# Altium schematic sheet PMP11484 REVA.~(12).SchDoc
size 431 x 279 mm; Date: Not shown in title block; ApprovedBy: Not shown in title block; CheckedBy: Not shown in title block; Author: Not shown in title block; CompanyName: Not shown in title block; Engineer: Not shown in title block; Organization: Not shown in title block; Address1: Not shown in title block; Address2: Not shown in title block; Address3: Not shown in title block; Address4: Not shown in title block; DocumentNumber: 1; Revision: Use project parameter SCH_Rev; SheetNumber: 1; SheetTotal: 1; PageSetup: Record=PageOptions¦CenterHorizontal=True¦CenterVertical=True¦PrintScale=1.00¦XCorrection=1.00¦YCorrection=1.00¦PrintKind=0¦BorderSize=5000000¦LeftOffset=0¦BottomOffset=0¦Orientation=2¦PaperLength=1000¦PaperWidth=1000¦Scale=100¦PaperSource=15¦PrintQuality=600¦MediaType=1¦DitherType=10¦PaperKind=Letter¦PrintScaleMode=1
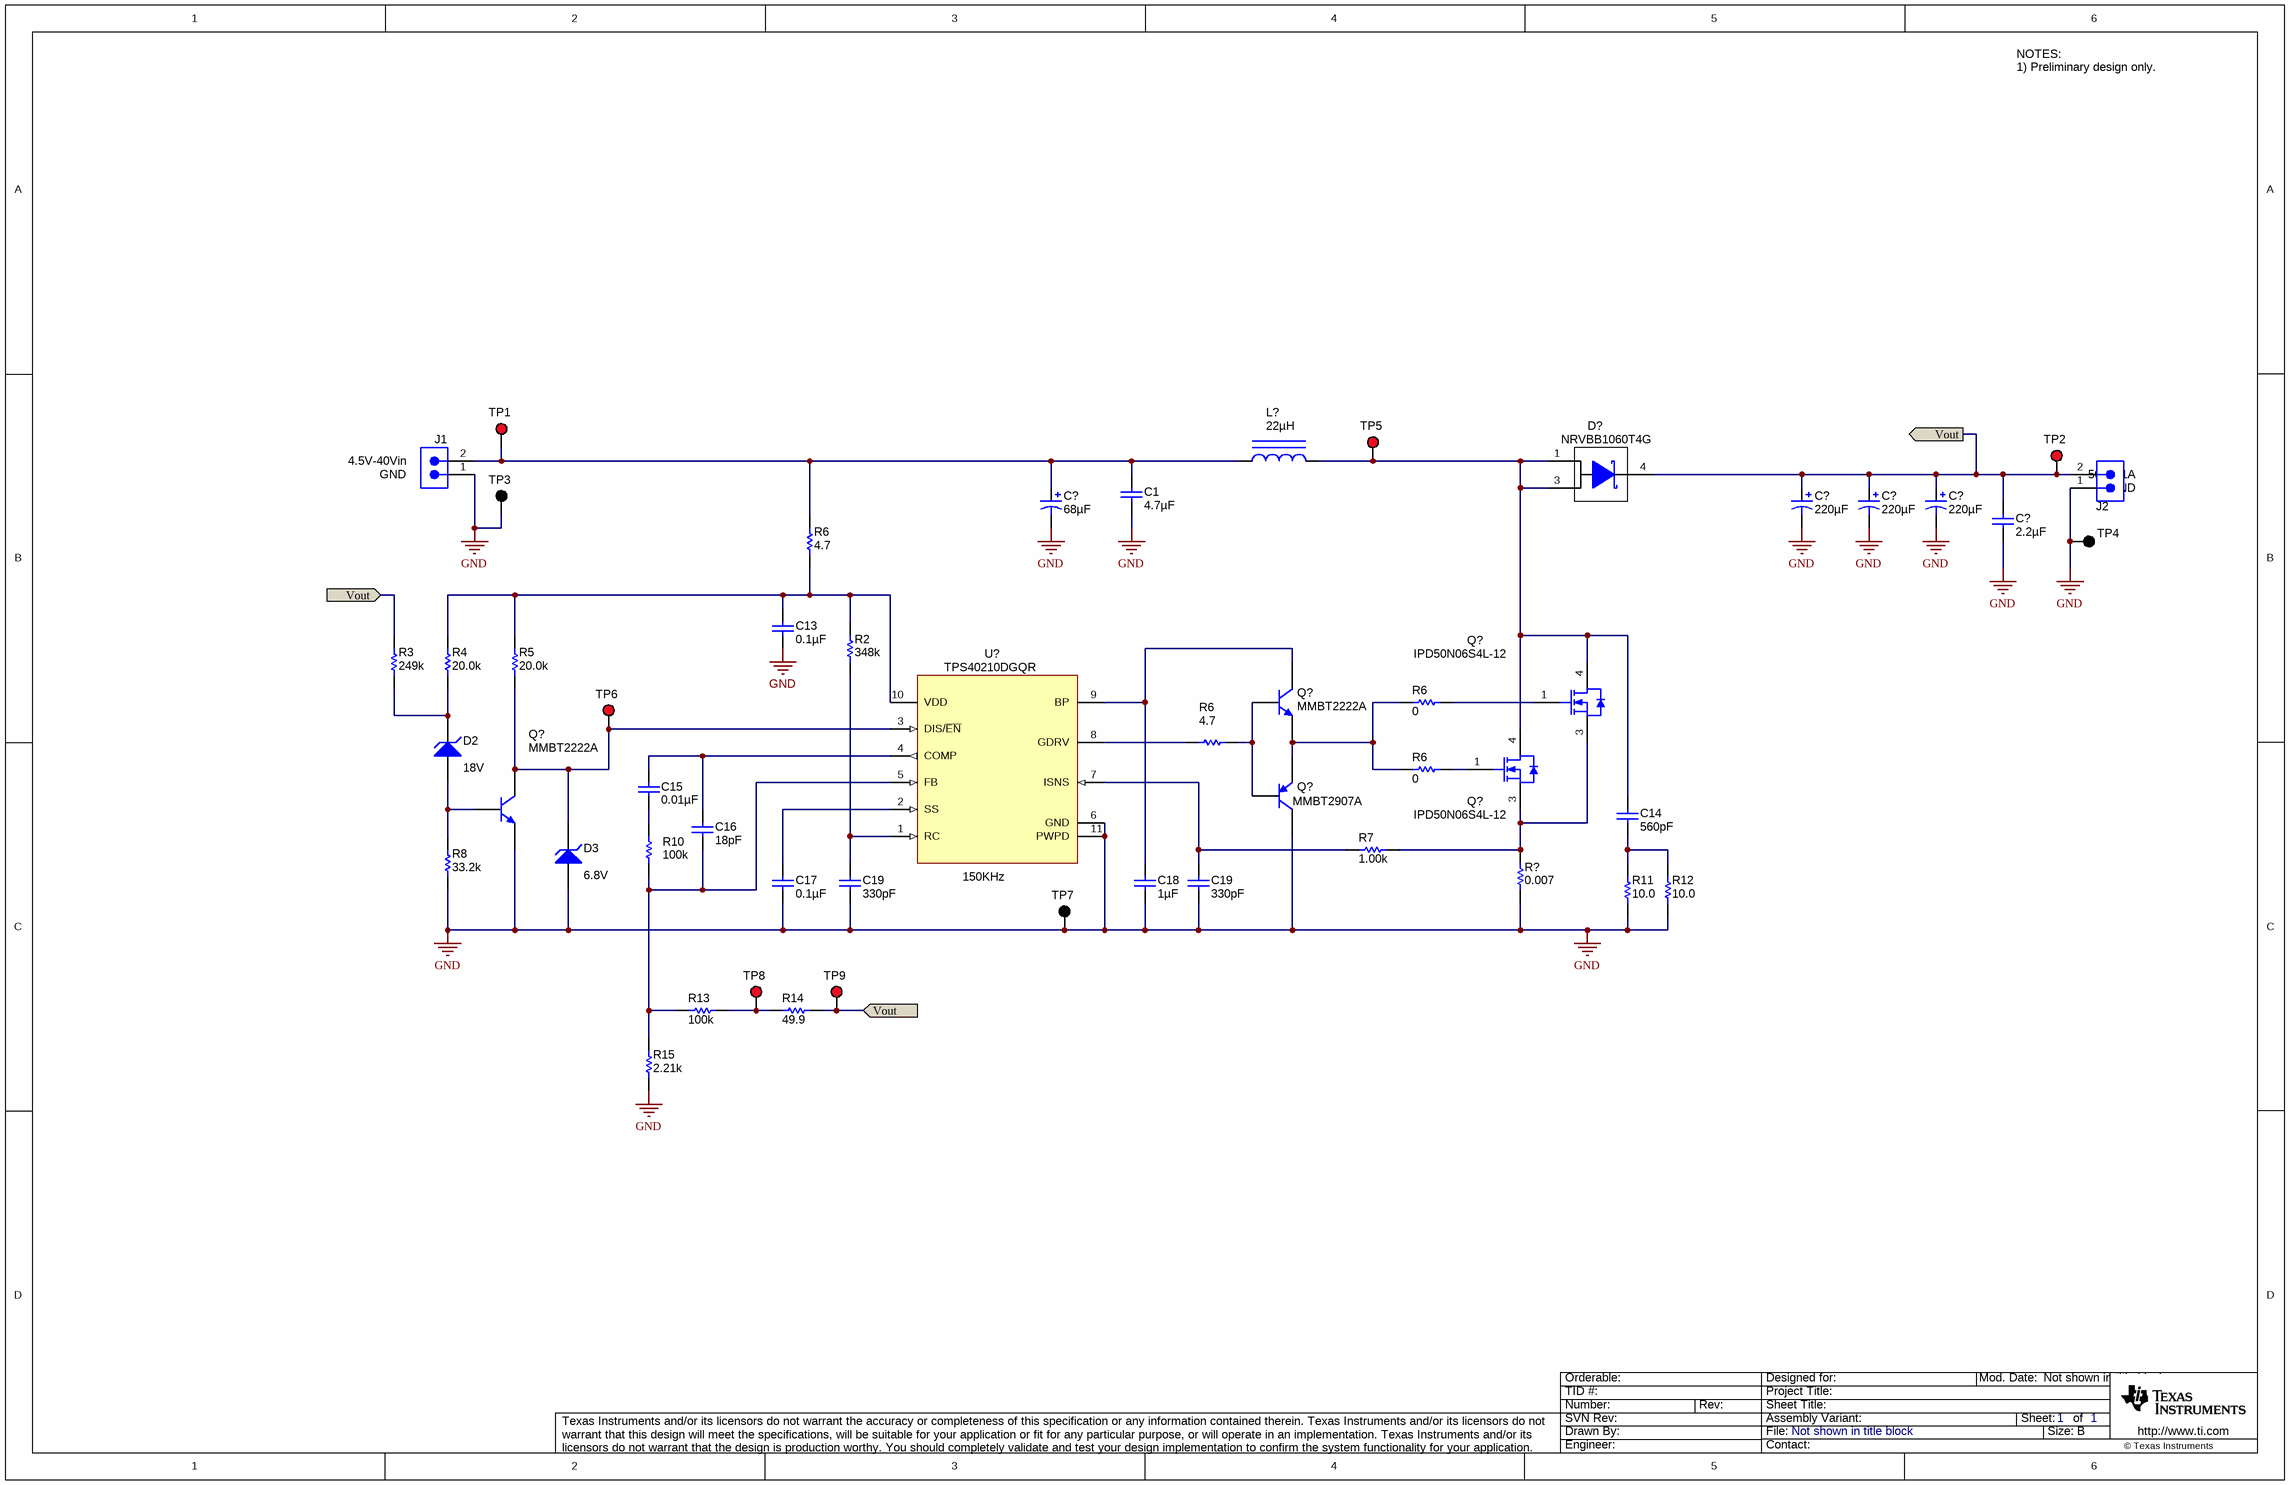
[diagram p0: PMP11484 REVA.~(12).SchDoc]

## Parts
(Parts that share a designator on the sheet are numbered #1, #2 ... from top to bottom, then left to right.)
C1  ValueDisplayed: 4.7µF  [1210]  (hidden comment: C3225X7R1H475M250AB)
C13  ValueDisplayed: 0.1µF  [0603]  (hidden comment: C1608X7R1H104K)
C14  ValueDisplayed: 560pF  [0603]  (hidden comment: C1608C0G1H561J)
C15  ValueDisplayed: 0.01µF  [0603]  (hidden comment: C1608X7R1H103K)
C16  ValueDisplayed: 18pF  [0603]  (hidden comment: C1608C0G1H180J)
C17  ValueDisplayed: 0.1µF  [0603]  (hidden comment: C1608X7R1H104K)
C18  ValueDisplayed: 1µF  [0603]  (hidden comment: C1608X7R1C105K)
C19#1  ValueDisplayed: 330pF  [0603]  (hidden comment: C1608C0G1H331J)
C19#2  ValueDisplayed: 330pF  [0603]  (hidden comment: C1608C0G1H331J)
C?#1  ValueDisplayed: 68µF  [SM_RADIAL_8MM]  (hidden comment: EEHZA1H680P)
C?#2  ValueDisplayed: 220µF  [BT_1250x2500]  (hidden comment: UBT1K221MHD1TO)
C?#3  ValueDisplayed: 220µF  [BT_1250x2500]  (hidden comment: UBT1K221MHD1TO)
C?#4  ValueDisplayed: 220µF  [BT_1250x2500]  (hidden comment: UBT1K221MHD1TO)
C?#5  ValueDisplayed: 2.2µF  [1210]  (hidden comment: GRM32ER72A225KA35L)
D2  value 18V  [SOD-123]  (hidden comment: MMSZ5248B)
D3  value 6.8V  [SOD-123]  (hidden comment: MMSZ5235B)
D?  NRVBB1060T4G  [DDPAK]
J1  ED555/2DS  [TERM_BLK_ED555-2DS]  (value not drawn)
J2  ED555/2DS  [TERM_BLK_ED555-2DS]  (value not drawn)
L?  ValueDisplayed: 22µH  [IHLP8787MZ]  (hidden comment: IHLP8787MZER220M5A)
Q?#1  MMBT2222A  [SOT-23]
Q?#2  IPD50N06S4L-12  [DPAK]
Q?#3  IPD50N06S4L-12  [DPAK]
Q?#4  MMBT2907A  [SOT-23]
Q?#5  MMBT2222A  [SOT-23]
R2  ValueDisplayed: 348k  [0603]  (hidden comment: CRCW0603348KFKEA)
R3  value 249k  [0603]  (hidden comment: CRCW0603249KFKEA)
R4  value 20.0k  [0603]  (hidden comment: CRCW060320K0FKEA)
R5  value 20.0k  [0603]  (hidden comment: CRCW060320K0FKEA)
R6#1  value 4.7  [0603]  (hidden comment: CRCW06034R70JNEA)
R6#2  ValueDisplayed: 0  [0603]  (hidden comment: CRCW06030000Z0EA)
R6#3  value 4.7  [0603]  (hidden comment: CRCW06034R70JNEA)
R6#4  ValueDisplayed: 0  [0603]  (hidden comment: CRCW06030000Z0EA)
R7  value 1.00k  [0603]  (hidden comment: CRCW06031K00FKEA)
R8  value 33.2k  [0603]  (hidden comment: CRCW060333K2FKEA)
R10  value 100k  [0603]  (hidden comment: CRCW0603100KFKEA)
R11  value 10.0  [1206]  (hidden comment: CRCW120610R0FKEA)
R12  value 10.0  [1206]  (hidden comment: CRCW120610R0FKEA)
R13  value 100k  [0603]  (hidden comment: CRCW0603100KFKEA)
R14  value 49.9  [0603]  (hidden comment: CRCW060349R9FKEA)
R15  value 2.21k  [0603]  (hidden comment: CRCW06032K21FKEA)
R?  ValueDisplayed: 0.007  [2512]  (hidden comment: WSL25127L000FEA)
TP1  5000  [Keystone5000]  (value not drawn)
TP2  5000  [Keystone5000]  (value not drawn)
TP3  5001  [Keystone5001]  (value not drawn)
TP4  5001  [Keystone5001]  (value not drawn)
TP5  5000  [Keystone5000]  (value not drawn)
TP6  5000  [Keystone5000]  (value not drawn)
TP7  5001  [Keystone5001]  (value not drawn)
TP8  5000  [Keystone5000]  (value not drawn)
TP9  5000  [Keystone5000]  (value not drawn)
U?  TPS40210DGQR  [DGQ0010D_N]

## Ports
Vout

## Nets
GND: C1.1 C13.2 C17.2 C18.2 C19#1.2 C19#2.2 C?#1.2(-) C?#2.2(-) C?#3.2(-) C?#4.2(-) C?#5.2 D3.2(A) J1.1 J2.1 Q?#4.3(C) Q?#5.2(E) R8.1 R11.1 R12.1 R15.1 R?.1 TP3.1 TP4.1 TP7.1 U?.6(GND) U?.11(PWPD)
Vout: C?#2.1(+) C?#3.1(+) C?#4.1(+) C?#5.1 D?.4(K) J2.2 R3.2 R14.1 TP2.1 TP9.1 ; port Vout
NetC1_2: C1.2 C?#1.1(+) J1.2 L?.1 R6#1.2 TP1.1
NetC13_1: C13.1 R2.2 R4.2 R5.2 R6#1.1 U?.10(VDD)
NetC14_1: C14.1 R11.2 R12.2
NetC14_2: C14.2 D?.1(A) D?.3(A) L?.2 Q?#2.4(D) Q?#3.4(D) TP5.1
NetC15_1: C15.1 R10.1
NetC15_2: C15.2 C16.2 U?.4(COMP)
NetC16_1: C16.1 R10.2 R13.2 R15.2 U?.5(FB)
NetC17_1: C17.1 U?.2(SS)
NetC18_1: C18.1 Q?#1.3(C) U?.9(BP)
NetC19#1_1: C19#1.1 R2.1 U?.1(RC)
NetC19#2_1: C19#2.1 R7.2 U?.7(ISNS)
NetD2_1: D2.1(K) R3.1 R4.1
NetD2_2: D2.2(A) Q?#5.1(B) R8.2
NetD3_1: D3.1(K) Q?#5.3(C) R5.1 TP6.1 U?.3(DIS/~{EN})
NetQ?#1_1: Q?#1.1(B) Q?#4.1(B) R6#3.2
NetQ?#1_2: Q?#1.2(E) Q?#4.2(E) R6#2.1 R6#4.1
NetQ?#2_1: Q?#2.1(G) R6#2.2
NetQ?#2_3: Q?#2.3(S) Q?#3.3(S) R7.1 R?.2
NetQ?#3_1: Q?#3.1(G) R6#4.2
NetR6#3_1: R6#3.1 U?.8(GDRV)
NetR13_1: R13.1 R14.2 TP8.1

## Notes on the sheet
- NOTES:
  1) Preliminary design only.
- (near J1) 4.5V-40Vin
- (near J1) GND
- (near J2) 50V@1A
- (near J2) GND
- (near U?) 150KHz

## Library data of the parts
C1 = C3225X7R1H335M: CAP, CERM, 4.7uF, 50V, +/-20%, X7R, 1210; Manufacturer: TDK; Polarized: N; CompType: Capacitor; U/M: EA; Cap_F: 0.0000033; Tolerance_%: 20; Value1: Unknown; VDC_V: 50; TaMin_C: -55; TaMax_C: 125
C13 C17 = C1608X7R1H104K: CAP, CERM, 0.1uF, 50V, +/-10%, X7R, 0603; Manufacturer: TDK; Polarized: N; CompType: Capacitor; U/M: EA; Cap_F: 0.0000001; Tolerance_%: 10; ESR_Ohm: 0.017; Value1: 0.017 ohm; VDC_V: 50; TaMin_C: -55; TaMax_C: 125
C14 = C1608C0G1H561J: CAP, CERM, 560pF, 50V, +/-5%, C0G/NP0, 0603; Manufacturer: TDK; Polarized: N; CompType: Capacitor; U/M: EA; Cap_F: 0.00000000056; Tolerance_%: 5; ESR_Ohm: 0.0858; Value1: 0.0858 ohm; VDC_V: 50; TaMin_C: -55; TaMax_C: 125
C15 = C1608X7R1H103K: CAP, CERM, 0.01uF, 50V, +/-10%, X7R, 0603; Manufacturer: TDK; Polarized: N; CompType: Capacitor; U/M: EA; Cap_F: 0.00000001; Tolerance_%: 10; ESR_Ohm: 0.0539; Value1: 0.0539 ohm; VDC_V: 50; TaMin_C: -55; TaMax_C: 125
C16 = C1608C0G1H180J: CAP, CERM, 18pF, 50V, +/-5%, C0G/NP0, 0603; Manufacturer: TDK; Polarized: N; CompType: Capacitor; U/M: EA; Cap_F: 0.000000000018; Tolerance_%: 5; ESR_Ohm: 0.4028; Value1: 0.4028 ohm; VDC_V: 50; TaMin_C: -55; TaMax_C: 125
C18 = C1608X7R1C105K: CAP, CERM, 1uF, 16V, +/-10%, X7R, 0603; Manufacturer: TDK; Polarized: N; CompType: Capacitor; U/M: EA; Cap_F: 0.000001; Tolerance_%: 10; ESR_Ohm: 0.0057; Value1: 0.0057 ohm; VDC_V: 16; TaMin_C: -55; TaMax_C: 125
C19#1 C19#2 = C1608C0G1H331J: CAP, CERM, 330 pF, 50 V, +/- 5%, C0G/NP0, 0603; Manufacturer: TDK; Polarized: N; CompType: Capacitor; Value: 330pF; U/M: EA; Cap_F: 0.00000000033; Tolerance_%: 5; ESR_ohm: 0.1096; Value1: 0.1096 ohm; VDC_V: 50; Value2: 50V; TaMin_C: -55; TaMax_C: 125; AEC Category: Q200
C?#1 = EEHZA1H680P: CAP, Polymer Hybrid, 68 µF, 50 V, +/- 20%, 30 ohm, 8x10 SMD; Manufacturer: Panasonic; Polarized: Y; CompType: Capacitor; Value: 68uF; U/M: EA; Cap_F: 0.000068; Tolerance_%: 20; Value1: 30 ohm; VDC_V: 50; Value2: 50V; ESR_ohm: 30; IRMS_A: 1.8; TaMin_C: -55; TaMax_C: 105; AEC Category: Q200
C?#2-C?#4 = UBT1H471MHD1TO: CAP, AL, 470 µF, 80 V, +/- 20%, 0.180 ohm, 1.24A, AEC-Q200 Grade 1, TH; Manufacturer: Nichicon; Polarized: Y; CompType: Capacitor; Value: 220uF; U/M: EA; Cap_F: 0.00047; Tolerance_%: 20; VDC_V: 80; Value2: 80V; TaMin_C: -40; TaMax_C: 125; Cap_Case: 12.5x25mm; AEC Category: Q200; AEC Grade: 1
C?#5 = GRM32ER72A225KA35L: CAP, CERM, 2.2 µF, 100 V, +/- 10%, X7R, 1210; Manufacturer: MuRata; Polarized: N; CompType: Capacitor; Value: 2.2uF; U/M: EA; Cap_F: 0.0000022; Tolerance_%: 10; ESR_ohm: 0.007; Value1: 0.007 ohm; VDC_V: 100; Value2: 100V; IRMS_A: 4.4; TaMin_C: -55; TaMax_C: 125; AEC Category: Q200
D2 = MMSZ5248B-7-F: Diode, Zener, 18V, 500mW, SOD-123; Manufacturer: Diodes Inc.; U/M: EA; Power_W: 0.5; Vz_V: 18; Value1: 0.5W; RJA_CperW: 350
D3 = MMSZ5231B-7-F: Diode, Zener, 6.8V, 500mW, SOD-123; Manufacturer: Diodes Inc.; U/M: EA; Power_W: 0.5; Vz_V: 6.8; Value1: 0.5W; RJA_CperW: 350
D? = MBRB2515LT4G: Diode, Schottky, 60V, 10A, DDPAK; Manufacturer: ON Semi; U/M: EA; Vf_V: 0.6; Value2: 0.6V; Io_A: 10; Vr_V: 60; TJmax_C: 100; RJC_CperW: 1; AEC Category: Q101
J1 J2 = ED555/2DS: Terminal Block, 6A, 3.5mm Pitch, 2-Pos, TH; Manufacturer: On-Shore Technology, Inc.; SymbolCreator: a0412235; CompType: Connector; U/M: EA
L? = IHLP8787MZE470M51: Inductor, Shielded, 22 µH, 16 A, 0.0106 ohm, SMD; Manufacturer: Vishay-Dale; Value: 22uH; Value2: 16A
Q?#1 Q?#5 = MMBT2222A, Fairchild Semiconductor: Transistor, NPN, 40 V, 0.15 A, SOT-23; CompType: BJT; PNP: 0; NPN: 1; Vceo_V: 40; Vcesat1_V: 0.3; Value: 40 V; IcRated_A: 0.15; Value1: 0.15 A; HfeMax: 300; TaMin_C: -55; TaMax_C: 150; U/M: EA; AEC Category: Q101
Q?#2 Q?#3 = IPD50R280CE: MOSFET, N-CH, 60 V, 0.012 Ohms, AEC-Q101, DPAK; Manufacturer: Infineon Technologies; Alternate Manufacturer: None; U/M: EA; ChType: N; Value: 60V; VdsMax_V: 60; QgTyp_nC: 32.6; Vgs_V: 16; IdsMax_A: 13; AEC Category: Q101
Q?#4 = MMBT2907A, Fairchild Semiconductor: Transistor, PNP, 60 V, 0.8 A, SOT-23; CompType: BJT; PNP: 1; NPN: 0; Vceo_V: 60; Vcesat1_V: 1.6; Value: 60 V; IcRated_A: 0.8; Value1: 0.8 A; HfeMax: 300; TaMin_C: -55; TaMax_C: 150; U/M: EA; AEC Category: Q101
R2 = CRCW0603348KFKEA: RES, 348 k, 1%, 0.1 W, 0603; Manufacturer: Vishay-Dale; CompType: Resistor; Value: 348k; Res_ohm: 348000; Tolerance_%: 1; Power_W: 0.1; Value2: 0.1W; VDC_V: 75; TempCo: 100 ppm/C; EIA_Code: E96; U/M: EA; AEC Category: Q200
R3 = CRCW0603249KFKEA: RES, 249k ohm, 1%, 0.1W, 0603; Manufacturer: Vishay-Dale; CompType: Resistor; Res_ohm: 249000; Tolerance_%: 1; Power_W: 0.1; VDC_V: 75; TempCo: 100 ppm/C; EIA_Code: E96; U/M: EA
R4 R5 = CRCW060320K0FKEA: RES, 20.0k ohm, 1%, 0.1W, 0603; Manufacturer: Vishay-Dale; CompType: Resistor; Res_ohm: 20000; Value_Code: 20k0; Tolerance_%: 1; Power_W: 0.1; VDC_V: 75; TempCo: 100 ppm/C; EIA_Code: E96; U/M: EA
R6#1 R6#3 = CRCW06034R70JNEA: RES, 4.7 ohm, 5%, 0.1W, 0603; Manufacturer: Vishay-Dale; CompType: Resistor; Value_Code: 4R70; Tolerance_%: 5; Power_W: 0.1; VDC_V: 75; TempCo: 200 ppm/C; EIA_Code: E24; U/M: EA
R6#2 R6#4 = CRCW06030000Z0EA: RES, 0, 5%, 0.1 W, 0603; Manufacturer: Vishay-Dale; CompType: Resistor; Value: 0; Value_Code: 0000; Tolerance_%: 5; Power_W: 0.1; Value2: 0.1W; VDC_V: 75; TempCo: 200 ppm/C; EIA_Code: E24; U/M: EA; AEC Category: Q200
R7 = CRCW06031K00FKEA: RES, 1.00k ohm, 1%, 0.1W, 0603; Manufacturer: Vishay-Dale; CompType: Resistor; Res_ohm: 1000; Value_Code: 1k00; Tolerance_%: 1; Power_W: 0.1; VDC_V: 75; TempCo: 100 ppm/C; EIA_Code: E96; U/M: EA
R8 = CRCW060333K2FKEA: RES, 33.2k ohm, 1%, 0.1W, 0603; Manufacturer: Vishay-Dale; CompType: Resistor; Res_ohm: 33200; Value_Code: 33k2; Tolerance_%: 1; Power_W: 0.1; VDC_V: 75; TempCo: 100 ppm/C; EIA_Code: E96; U/M: EA
R10 R13 = CRCW0603100KFKEA: RES, 100k ohm, 1%, 0.1W, 0603; Manufacturer: Vishay-Dale; CompType: Resistor; Res_ohm: 100000; Tolerance_%: 1; Power_W: 0.1; VDC_V: 75; TempCo: 100 ppm/C; EIA_Code: E96; U/M: EA
R11 R12 = CRCW120610R0FKEA: RES, 10.0 ohm, 1%, 0.25W, 1206; Manufacturer: Vishay-Dale; CompType: Resistor; Res_ohm: 10; Value_Code: 10R0; Tolerance_%: 1; Power_W: 0.25; VDC_V: 200; TempCo: 100 ppm/C; EIA_Code: E96; U/M: EA
R14 = CRCW060349R9FKEA: RES, 49.9 ohm, 1%, 0.1W, 0603; Manufacturer: Vishay-Dale; CompType: Resistor; Value_Code: 49R9; Tolerance_%: 1; Power_W: 0.1; VDC_V: 75; TempCo: 100 ppm/C; EIA_Code: E96; U/M: EA
R15 = CRCW06032K21FKEA: RES, 2.21k ohm, 1%, 0.1W, 0603; Manufacturer: Vishay-Dale; CompType: Resistor; Res_ohm: 2210; Value_Code: 2k21; Tolerance_%: 1; Power_W: 0.1; VDC_V: 75; TempCo: 100 ppm/C; EIA_Code: E96; U/M: EA
R? = WSL25129L000FEA18: RES, 0.007, 1%, 2 W, 2512; Manufacturer: Vishay-Dale; CompType: Resistor; Value: 0.007; Value_Code: 7L000; Tolerance_%: 1; Power_W: 2; Value2: 2W; TempCo: 75 ppm/C; EIA_Code: E96; U/M: EA; AEC Category: Q200
TP1 TP2 TP5 TP6 TP8 TP9 = 5000: Test Point, TH, Miniature, Red; Manufacturer: Keystone; CompType: Test Point Loop; U/M: EA
TP3 TP4 TP7 = 5001: Test Point, TH, Miniature, Black; Manufacturer: Keystone; CompType: Test Point Loop; U/M: EA
U? = TPS40210DGQR: 4.5-V TO 52-V INPUT CURRENT MODE BOOST CONTROLLER, DGQ0010D; Manufacturer: Texas Instruments; SymbolCreator: a0412235; CompType: IC; U/M: EA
